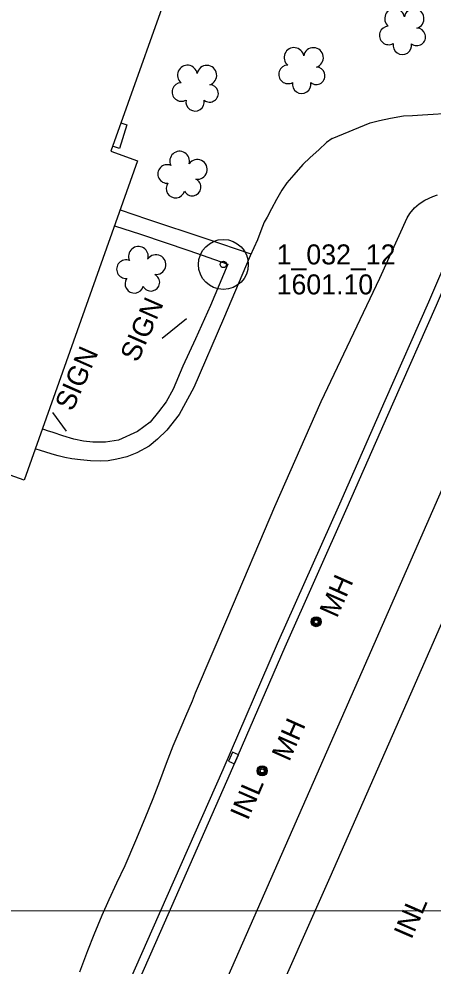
# Model space of a CAD drawing. Extents: x 189384 to 193282, y 256970 to 260388.
# Drawn here: x 190477.3 to 190601.7, y 257994.7 to 258279 of the extents above; entities that cross this region are included whole.
import ezdxf

# ---------------------------------------------------------------- set-up
doc = ezdxf.new("R2010")
doc.units = 0
for name, color, linetype in [('E_DRN_Grate', 7, 'Continuous'), ('E_DWY', 7, 'Continuous'), ('E_LAND_Vegetation', 7, 'Continuous'), ('E_MAP_GridLines', 7, 'Continuous'), ('E_MAP_PassPoints', 7, 'Continuous'), ('E_MISCPROP', 7, 'Continuous'), ('E_MISCPROP_HvyLine', 7, 'Continuous'), ('E_MISCPROP_Railing', 7, 'Continuous'), ('E_PATH_Sidewalk', 7, 'Continuous'), ('E_RDWY', 7, 'Continuous')]:
    doc.layers.add(name, color=color, linetype=linetype)

# ---------------------------------------------------------------- blocks, each defined once
blk = doc.blocks.new('PP_3')
at = {"layer": 'E_MAP_PassPoints'}
for radius in [7.5, 0.96]:
    blk.add_circle((0, 0), radius, dxfattribs=at)
blk = doc.blocks.new('TREE_10')
at = {"layer": 'E_LAND_Vegetation'}
for centre, radius, start, end in [((-1.47, 4.28), 2.78, 1.3947, 209.1677), ((-4.47, 0.2), 2.78, 78.0717, 279.0828), ((3.57, 2.42), 2.97, 278.4238, 139.6577), ((-2.01, -4.2), 2.61, 140.7799, 358.7125), ((3.46, -3.43), 2.97, 196.0746, 79.0479)]:
    blk.add_arc(centre, radius, start, end, dxfattribs=at)
blk = doc.blocks.new('INLT_4')
at = {"layer": 'E_MISCPROP_Railing'}
blk.add_lwpolyline([(3, -2), (3, 0), (0, 0), (0, -2), (3, -2)], dxfattribs=at)
blk = doc.blocks.new('INL_5')
at = {"layer": 'E_MISCPROP_Railing'}
blk.add_text('INL', height=6, rotation=360, dxfattribs=at).set_placement((-5.79, -2.75))
blk = doc.blocks.new('SIGN_1')
at = {"layer": 'E_MISCPROP'}
blk.add_text('SIGN', height=6, rotation=360, dxfattribs=at).set_placement((-9.61, -3.01))
blk = doc.blocks.new('TREE_3')
at = {"layer": 'E_LAND_Vegetation'}
for centre, radius, start, end in [((-1.47, 4.28), 2.78, 1.3945, 209.1675), ((-4.47, 0.2), 2.78, 78.0715, 279.0825), ((3.57, 2.42), 2.97, 278.4236, 139.6575), ((-2.01, -4.2), 2.61, 140.7796, 358.7122), ((3.46, -3.43), 2.97, 196.0744, 79.0477)]:
    blk.add_arc(centre, radius, start, end, dxfattribs=at)
blk = doc.blocks.new('MHO')
at = {"layer": 'E_DRN_Grate'}
for centre, radius in [((0.04, -0.06), 1.5), ((0.04, -0.06), 1.22), ((0.04, -0.07), 0.968), ((0.01, -0.08), 0.605)]:
    blk.add_circle(centre, radius, dxfattribs=at)

msp = doc.modelspace()

# ---------------------------------------------------------------- linework, layer by layer
at = {"layer": 'E_DWY'}
for points in [[(190571.41, 258243.16), (190582.79, 258247.78), (190585.57, 258248.49), (190588.91, 258249.27), (190592.75, 258249.91), (190595.45, 258250.07), (190598.48, 258250.18), (190601.73, 258250.45), (190604.81, 258250.59), (190607.83, 258250.14), (190610.29, 258249.63), (190612.32, 258249.6), (190614.56, 258249.35), (190615.62, 258249.32), (190618.35, 258249.03), (190624.63, 258249.31)], [(190571.41, 258243.16), (190569.71, 258241.88), (190567.38, 258239.77), (190564.71, 258237.43), (190562.6, 258235.37), (190559.82, 258232.24), (190557.78, 258229.83), (190556.25, 258227.64), (190554.62, 258224.81), (190553.13, 258222.04), (190551.8, 258219.56), (190550.98, 258218), (190549.95, 258215.44), (190548.93, 258212.67), (190546.71, 258207.88), (190538.7, 258189.04), (190529.81, 258168.38), (190525.38, 258160.31), (190521.71, 258155.62), (190518.91, 258152.87), (190516.42, 258150.76), (190512.68, 258148.73), (190509.69, 258147.52), (190506.66, 258146.84), (190504.11, 258146.39), (190501.89, 258146.23), (190498.78, 258146.33), (190495.8, 258146.64), (190493.2, 258146.97), (190491.05, 258147.33), (190489.09, 258147.85), (190487.25, 258148.4), (190485.12, 258149.09), (190484.13, 258149.39), (190482.17, 258149.97)], [(190495.6, 257992.94), (190498.03, 257999.34), (190499.92, 258004.21), (190502.31, 258010), (190504.45, 258014.7), (190506.73, 258019.73), (190509.2, 258024.92), (190512.4, 258032.39), (190515.25, 258039.11), (190517.59, 258045.04), (190519.59, 258050.25), (190521.65, 258055.66), (190523.6, 258060.77), (190525.99, 258066.46), (190527.43, 258069.76), (190529.39, 258074.36), (190530.37, 258076.76), (190540.03, 258099.46), (190554.13, 258132.68), (190568.11, 258164.14), (190585.63, 258201.16), (190593.93, 258219.34), (190594.7, 258220.58), (190596.07, 258222.31), (190597.47, 258223.54), (190599.2, 258224.65), (190601.57, 258225.7), (190603.01, 258226.17)]]:
    msp.add_lwpolyline(points, dxfattribs=at)
at = {"layer": 'E_MAP_GridLines'}
for p in [(189647.41, 258010.74), (190147.4, 258011.09)]:
    msp.add_line(p, (191647.4, 258012.16), dxfattribs=at)
at = {"layer": 'E_MISCPROP'}
for p, q in [((190520.3, 258183.23), (190527.67, 258189.09)), ((190487.4, 258160.86), (190491.48, 258155.27))]:
    msp.add_line(p, q, dxfattribs=at)
at = {"layer": 'E_MISCPROP_HvyLine'}
msp.add_lwpolyline([(190464.41, 258319.89), (190525.78, 258298.05), (190504.87, 258239.32), (190512.95, 258236.44), (190478.83, 258140.59), (190464.76, 258145.6), (190470.78, 258162.5), (190410.31, 258184.02), (190408.82, 258179.84), (190391.38, 258186.05), (190396.77, 258201.2), (190400.52, 258199.86), (190413.48, 258236.27), (190422.67, 258233), (190433.87, 258264.46), (190443.47, 258261.04)], close=True, dxfattribs=at)
at = {"layer": 'E_PATH_Sidewalk'}
for points in [[(190507.89, 258247.79), (190509.67, 258247.19), (190507.49, 258240.11), (190505.41, 258240.82)], [(190507.71, 258221.71), (190515.88, 258218.94), (190533.47, 258213.08), (190546.99, 258208.48)], [(190506.01, 258216.93), (190513.8, 258214.43), (190528.31, 258209.48), (190540.01, 258205.39), (190534.81, 258192.95), (190530.31, 258183.02), (190526.54, 258174.76), (190523.59, 258167.92), (190521.47, 258164.12), (190519.22, 258161.04), (190516.72, 258157.96), (190512.91, 258155.14), (190507.23, 258152.56), (190503.33, 258151.99), (190499.53, 258152), (190496.66, 258152.29), (190493.77, 258152.83), (190490.49, 258153.85), (190487.61, 258154.89), (190485.93, 258155.41), (190484.3, 258155.94)]]:
    msp.add_lwpolyline(points, dxfattribs=at)
at = {"layer": 'E_RDWY'}
for points in [[(190486.34, 257929.3), (190500.99, 257962.31), (190519.93, 258005.2), (190540.88, 258052.68), (190557.27, 258090.57), (190575.92, 258132.39), (190589.56, 258163.44), (190602.68, 258193.06), (190616.68, 258225.7)], [(190498.7, 257963.32), (190517.65, 258006.21), (190538.59, 258053.68), (190554.98, 258091.58), (190573.63, 258133.41), (190587.27, 258164.44), (190600.39, 258194.06), (190614.38, 258226.68)], [(190639.31, 258218.07), (190609.41, 258149.39), (190580.27, 258083.06), (190547.78, 258009.13), (190519.09, 257944.03), (190494.25, 257887.28), (190465.55, 257822.08), (190442.19, 257769.07), (190419.9, 257718.5), (190394.49, 257660.93), (190374.24, 257614.8), (190349, 257556.99), (190323.12, 257498.57), (190298.43, 257442.39), (190276.94, 257393.85), (190259.86, 257355.22)], [(190647.06, 258194.52), (190624.13, 258142.92), (190594.92, 258076.29), (190570.69, 258021.28), (190551.11, 257977.35), (190533.78, 257937.86), (190511.8, 257887.72), (190488.43, 257834.81), (190463.86, 257779), (190437.37, 257718.32), (190410.84, 257658.32), (190384.1, 257597.28), (190367.03, 257558.94), (190342.84, 257503.57), (190317.05, 257445.11), (190294.43, 257394.4)]]:
    msp.add_lwpolyline(points, dxfattribs=at)

# ---------------------------------------------------------------- block references
at = {"layer": 'E_DRN_Grate'}
for p, rotation in [((190566.49, 258098.07), 66.02694835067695), ((190550.28, 258053.29), 66.02694863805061)]:
    msp.add_blockref('MHO', p, dxfattribs=dict(at, rotation=rotation))
at = {"layer": 'E_LAND_Vegetation'}
for p, xscale, yscale, rotation in [((190592.58, 258275.59), 1.0000013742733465, 1.0000013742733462, 90.72455388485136), ((190562.37, 258263.9), 1.000001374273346, 1.0000013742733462, 90.72455442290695), ((190530.35, 258258.61), 1.0000013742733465, 1.0000013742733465, 90.72455499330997)]:
    msp.add_blockref('TREE_10', p, dxfattribs=dict(at, xscale=xscale, yscale=yscale, rotation=rotation))
for p, rotation in [((190526.32, 258232.08), 66.02694907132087), ((190513.94, 258203.5), 66.02694929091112)]:
    msp.add_blockref('TREE_3', p, dxfattribs=dict(at, rotation=rotation))
at = {"layer": 'E_MAP_PassPoints', "rotation": -0.00010205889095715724}
msp.add_blockref('PP_3', (190538.69, 258205.33), dxfattribs=at)
msp.add_blockref('PP_3', (190538.69, 258205.33), dxfattribs=at)
at = {"layer": 'E_MISCPROP'}
for p, rotation in [((190514.09, 258185.68), 66.26477211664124), ((190494.5, 258170.97), 66.26477246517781)]:
    msp.add_blockref('SIGN_1', p, dxfattribs=dict(at, rotation=rotation))
at = {"layer": 'E_MISCPROP_Railing'}
for name, p, xscale, yscale, rotation in [('INLT_4', (190543.25, 258058.15), 1.0000013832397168, 1.0000013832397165, -113.38898571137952), ('INL_5', (190545.79, 258044.58), 1.000001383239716, 1.0000013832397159, 66.61101424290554), ('INL_5', (190594.93, 258008.88), 1.0000013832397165, 1.0000013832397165, 66.61101336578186)]:
    msp.add_blockref(name, p, dxfattribs=dict(at, xscale=xscale, yscale=yscale, rotation=rotation))

# ---------------------------------------------------------------- texts
at = {"layer": 'E_DRN_Grate'}
for p in [(190572.81, 258098.94), (190558.46, 258055.85)]:
    msp.add_text('MH', height=6, rotation=66.027, dxfattribs=at).set_placement(p)
at = {"layer": 'E_MAP_PassPoints'}
for s, p in [('1_032_12', (190554.69, 258205.33)), ('1_032_12', (190554.69, 258205.33)), ('1601.10', (190554.69, 258196.33)), ('1601.10', (190554.69, 258196.33))]:
    msp.add_text(s, height=6, rotation=0, dxfattribs=at).set_placement(p)

doc.saveas('drawing.dxf')
